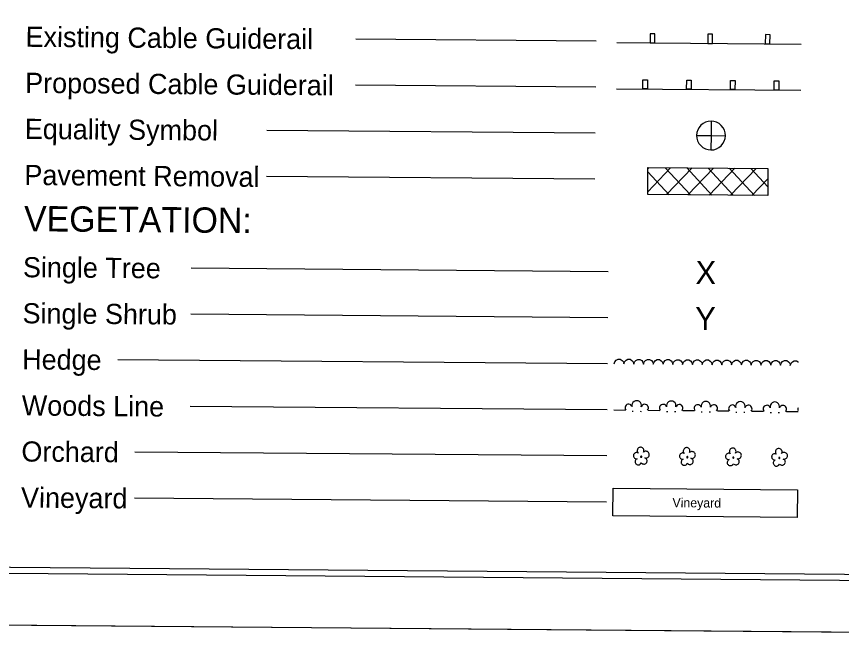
# Model space of a CAD drawing. Extents: x 1379453 to 1387082, y 594364 to 596664.
# Drawn here: x 1384828 to 1385545, y 594436 to 594983 of the extents above; entities that cross this region are included whole.
import ezdxf

# ---------------------------------------------------------------- set-up
doc = ezdxf.new("R2010")
doc.units = 0
for name, color, linetype in [('Sheet Cutting Line CELL', 7, 'Continuous'), ('Sheet Plot Border Inside CELL', 7, 'Continuous'), ('Sheet Plot Border Outside CELL', 7, 'Continuous'), ('Sheet Symbology CELL', 7, 'Continuous')]:
    doc.layers.add(name, color=color, linetype=linetype)

msp = doc.modelspace()

# ---------------------------------------------------------------- linework, layer by layer
at = {"layer": 'Sheet Cutting Line CELL'}
msp.add_line((1383695.45, 594463.89), (1387063.33, 594435.67), dxfattribs=at)
at = {"layer": 'Sheet Plot Border Inside CELL'}
msp.add_lwpolyline([(1383721.82, 594508.57), (1387054.71, 594480.65), (1387072.39, 596590.77), (1383739.5, 596618.7)], close=True, dxfattribs=at)
at = {"layer": 'Sheet Plot Border Outside CELL'}
msp.add_lwpolyline([(1383695.45, 594463.89), (1387063.33, 594435.67), (1387081.76, 596635.6), (1383713.88, 596663.81)], close=True, dxfattribs=at)
at = {"layer": 'Sheet Symbology CELL'}
for p, q in [((1385331.7, 594961.34), (1385123.11, 594963.08)), ((1385349.71, 594960.04), (1385509.71, 594958.7)), ((1385331.36, 594921.34), (1385122.77, 594923.09)), ((1385349.38, 594920.04), (1385509.37, 594918.7)), ((1385431.6, 594891.82), (1385431.49, 594879.32)), ((1385331.03, 594881.34), (1385045.79, 594883.73)), ((1385418.99, 594879.43), (1385431.49, 594879.32)), ((1385431.49, 594879.32), (1385431.39, 594866.82)), ((1385431.49, 594879.32), (1385443.99, 594879.22)), ((1385376.51, 594828.13), (1385376.71, 594851.53)), ((1385376.53, 594830.43), (1385396.41, 594851.37)), ((1385376.7, 594850.33), (1385377.81, 594851.52)), ((1385376.71, 594851.53), (1385480.9, 594850.66)), ((1385413.61, 594827.82), (1385391.81, 594851.41)), ((1385392.81, 594828), (1385415, 594851.21)), ((1385432.11, 594827.67), (1385410.4, 594851.25)), ((1385411.31, 594827.84), (1385433.6, 594851.05)), ((1385450.71, 594827.51), (1385428.9, 594851.09)), ((1385429.91, 594827.69), (1385452.1, 594850.9)), ((1385469.31, 594827.35), (1385447.4, 594850.94)), ((1385448.51, 594827.53), (1385470.6, 594850.74)), ((1385480.77, 594834.76), (1385466, 594850.78)), ((1385480.9, 594850.66), (1385480.71, 594827.26)), ((1385330.69, 594841.34), (1385045.45, 594843.73)), ((1385395.01, 594827.98), (1385376.68, 594847.93)), ((1385467.01, 594827.37), (1385480.83, 594841.86)), ((1385480.71, 594827.26), (1385376.51, 594828.13)), ((1385342.3, 594761.1), (1384980.06, 594764.14)), ((1385341.96, 594721.1), (1384979.72, 594724.14)), ((1385341.63, 594681.11), (1384916.27, 594684.67)), ((1385349.2, 594684.24), (1385350.81, 594685.13)), ((1385350.81, 594685.13), (1385352.71, 594685.11)), ((1385352.71, 594685.11), (1385354.3, 594684.1)), ((1385357.7, 594684.17), (1385359.31, 594685.06)), ((1385359.31, 594685.06), (1385361.21, 594685.04)), ((1385361.21, 594685.04), (1385362.8, 594684.03)), ((1385366.2, 594684.1), (1385367.81, 594684.99)), ((1385367.81, 594684.99), (1385369.71, 594684.97)), ((1385369.71, 594684.97), (1385371.3, 594683.96)), ((1385374.7, 594684.03), (1385376.31, 594684.92)), ((1385376.31, 594684.92), (1385378.21, 594684.9)), ((1385378.21, 594684.9), (1385379.8, 594683.89)), ((1385383.2, 594683.96), (1385384.81, 594684.84)), ((1385384.81, 594684.84), (1385386.71, 594684.83)), ((1385386.71, 594684.83), (1385388.3, 594683.81)), ((1385391.7, 594683.89), (1385393.31, 594684.77)), ((1385393.31, 594684.77), (1385395.21, 594684.76)), ((1385395.21, 594684.76), (1385396.8, 594683.74)), ((1385400.2, 594683.82), (1385401.81, 594684.7)), ((1385401.81, 594684.7), (1385403.71, 594684.69)), ((1385403.71, 594684.69), (1385405.3, 594683.67)), ((1385408.7, 594683.74), (1385410.31, 594684.63)), ((1385410.31, 594684.63), (1385412.21, 594684.61)), ((1385412.21, 594684.61), (1385413.8, 594683.6)), ((1385347.38, 594681.06), (1385347.99, 594682.95)), ((1385347.99, 594682.95), (1385349.2, 594684.24)), ((1385354.3, 594684.1), (1385355.39, 594682.79)), ((1385355.39, 594682.79), (1385355.78, 594681.09)), ((1385355.88, 594680.99), (1385356.49, 594682.88)), ((1385356.49, 594682.88), (1385357.7, 594684.17)), ((1385362.8, 594684.03), (1385363.89, 594682.72)), ((1385363.89, 594682.72), (1385364.28, 594681.02)), ((1385364.38, 594680.92), (1385364.99, 594682.81)), ((1385364.99, 594682.81), (1385366.2, 594684.1)), ((1385371.3, 594683.96), (1385372.39, 594682.65)), ((1385372.39, 594682.65), (1385372.78, 594680.94)), ((1385372.88, 594680.84), (1385373.49, 594682.74)), ((1385373.49, 594682.74), (1385374.7, 594684.03)), ((1385379.8, 594683.89), (1385380.89, 594682.58)), ((1385380.89, 594682.58), (1385381.28, 594680.87)), ((1385381.38, 594680.77), (1385381.99, 594682.67)), ((1385381.99, 594682.67), (1385383.2, 594683.96)), ((1385388.3, 594683.81), (1385389.39, 594682.51)), ((1385389.39, 594682.51), (1385389.78, 594680.8)), ((1385389.88, 594680.7), (1385390.49, 594682.6)), ((1385390.49, 594682.6), (1385391.7, 594683.89)), ((1385396.8, 594683.74), (1385397.89, 594682.43)), ((1385397.89, 594682.43), (1385398.28, 594680.73)), ((1385398.37, 594680.63), (1385398.99, 594682.53)), ((1385398.99, 594682.53), (1385400.2, 594683.82)), ((1385405.3, 594683.67), (1385406.39, 594682.36)), ((1385406.39, 594682.36), (1385406.78, 594680.66)), ((1385406.87, 594680.56), (1385407.49, 594682.45)), ((1385407.49, 594682.45), (1385408.7, 594683.74)), ((1385413.8, 594683.6), (1385414.89, 594682.29)), ((1385414.89, 594682.29), (1385415.28, 594680.59)), ((1385415.37, 594680.49), (1385415.99, 594682.38)), ((1385415.99, 594682.38), (1385417.2, 594683.67)), ((1385417.2, 594683.67), (1385418.81, 594684.56)), ((1385418.81, 594684.56), (1385420.71, 594684.54)), ((1385420.71, 594684.54), (1385422.3, 594683.53)), ((1385422.3, 594683.53), (1385423.39, 594682.22)), ((1385423.39, 594682.22), (1385423.77, 594680.52)), ((1385423.87, 594680.42), (1385424.49, 594682.31)), ((1385424.49, 594682.31), (1385425.7, 594683.6)), ((1385425.7, 594683.6), (1385427.31, 594684.49)), ((1385427.31, 594684.49), (1385429.21, 594684.47)), ((1385429.21, 594684.47), (1385430.8, 594683.46)), ((1385430.8, 594683.46), (1385431.89, 594682.15)), ((1385431.89, 594682.15), (1385432.27, 594680.45)), ((1385432.37, 594680.35), (1385432.99, 594682.24)), ((1385432.99, 594682.24), (1385434.2, 594683.53)), ((1385434.2, 594683.53), (1385435.81, 594684.42)), ((1385435.81, 594684.42), (1385437.71, 594684.4)), ((1385437.71, 594684.4), (1385439.3, 594683.39)), ((1385439.3, 594683.39), (1385440.39, 594682.08)), ((1385440.39, 594682.08), (1385440.77, 594680.38)), ((1385440.87, 594680.27), (1385441.49, 594682.17)), ((1385441.49, 594682.17), (1385442.7, 594683.46)), ((1385442.7, 594683.46), (1385444.31, 594684.35)), ((1385444.31, 594684.35), (1385446.21, 594684.33)), ((1385446.21, 594684.33), (1385447.8, 594683.32)), ((1385447.8, 594683.32), (1385448.89, 594682.01)), ((1385448.89, 594682.01), (1385449.27, 594680.3)), ((1385449.37, 594680.2), (1385449.99, 594682.1)), ((1385449.99, 594682.1), (1385451.2, 594683.39)), ((1385451.2, 594683.39), (1385452.81, 594684.27)), ((1385452.81, 594684.27), (1385454.71, 594684.26)), ((1385454.71, 594684.26), (1385456.3, 594683.25)), ((1385456.3, 594683.25), (1385457.39, 594681.94)), ((1385457.39, 594681.94), (1385457.77, 594680.23)), ((1385457.87, 594680.13), (1385458.49, 594682.03)), ((1385458.49, 594682.03), (1385459.7, 594683.32)), ((1385459.7, 594683.32), (1385461.31, 594684.2)), ((1385461.31, 594684.2), (1385463.21, 594684.19)), ((1385463.21, 594684.19), (1385464.8, 594683.17)), ((1385464.8, 594683.17), (1385465.89, 594681.86)), ((1385465.89, 594681.86), (1385466.27, 594680.16)), ((1385466.37, 594680.06), (1385466.99, 594681.96)), ((1385466.99, 594681.96), (1385468.2, 594683.25)), ((1385468.2, 594683.25), (1385469.81, 594684.13)), ((1385469.81, 594684.13), (1385471.71, 594684.12)), ((1385471.71, 594684.12), (1385473.3, 594683.1)), ((1385473.3, 594683.1), (1385474.39, 594681.79)), ((1385474.39, 594681.79), (1385474.77, 594680.09)), ((1385474.87, 594679.99), (1385475.49, 594681.88)), ((1385475.49, 594681.88), (1385476.7, 594683.17)), ((1385476.7, 594683.17), (1385478.31, 594684.06)), ((1385478.31, 594684.06), (1385480.21, 594684.05)), ((1385480.21, 594684.05), (1385481.8, 594683.03)), ((1385481.8, 594683.03), (1385482.89, 594681.72)), ((1385482.89, 594681.72), (1385483.27, 594680.02)), ((1385483.37, 594679.92), (1385483.99, 594681.81)), ((1385483.99, 594681.81), (1385485.2, 594683.1)), ((1385485.2, 594683.1), (1385486.81, 594683.99)), ((1385486.81, 594683.99), (1385488.71, 594683.97)), ((1385488.71, 594683.97), (1385490.3, 594682.96)), ((1385490.3, 594682.96), (1385491.39, 594681.65)), ((1385491.39, 594681.65), (1385491.77, 594679.95)), ((1385491.87, 594679.85), (1385492.49, 594681.74)), ((1385492.49, 594681.74), (1385493.7, 594683.03)), ((1385493.7, 594683.03), (1385495.31, 594683.92)), ((1385495.31, 594683.92), (1385497.21, 594683.9)), ((1385497.21, 594683.9), (1385498.8, 594682.89)), ((1385498.8, 594682.89), (1385499.89, 594681.58)), ((1385499.89, 594681.58), (1385500.27, 594679.88)), ((1385500.37, 594679.78), (1385500.99, 594681.67)), ((1385500.99, 594681.67), (1385502.2, 594682.96)), ((1385502.2, 594682.96), (1385503.81, 594683.85)), ((1385503.81, 594683.85), (1385505.71, 594683.83)), ((1385505.71, 594683.83), (1385507.3, 594682.82)), ((1385507.3, 594682.82), (1385507.4, 594682.72)), ((1385341.29, 594641.11), (1384979.05, 594644.14)), ((1385347.04, 594641.06), (1385357.04, 594640.98)), ((1385362.93, 594639.93), (1385363.93, 594639.92)), ((1385369.93, 594639.87), (1385370.93, 594639.86)), ((1385377.04, 594640.81), (1385387.04, 594640.72)), ((1385392.93, 594639.67), (1385393.93, 594639.67)), ((1385399.93, 594639.62), (1385400.93, 594639.61)), ((1385407.04, 594640.56), (1385417.04, 594640.47)), ((1385422.93, 594639.42), (1385423.93, 594639.41)), ((1385429.93, 594639.36), (1385430.93, 594639.36)), ((1385437.04, 594640.31), (1385447.04, 594640.22)), ((1385452.93, 594639.17), (1385453.93, 594639.16)), ((1385459.93, 594639.11), (1385460.93, 594639.1)), ((1385467.04, 594640.05), (1385477.04, 594639.97)), ((1385482.93, 594638.92), (1385483.93, 594638.91)), ((1385489.93, 594638.86), (1385490.93, 594638.85)), ((1385497.04, 594639.8), (1385507.04, 594639.72)), ((1385340.96, 594601.11), (1384931.1, 594604.54)), ((1385340.62, 594561.11), (1384930.76, 594564.54))]:
    msp.add_line(p, q, dxfattribs=at)
for points in [[(1387047.34, 596585.88), (1384047.45, 596611.02), (1384029.86, 594511.09), (1387029.75, 594485.96)], [(1385378.66, 594959.79), (1385382.66, 594959.76), (1385382.73, 594967.76), (1385378.73, 594967.79)], [(1385428.66, 594959.38), (1385432.66, 594959.34), (1385432.73, 594967.34), (1385428.73, 594967.37)], [(1385478.66, 594958.96), (1385482.66, 594958.92), (1385482.73, 594966.92), (1385478.73, 594966.96)], [(1385372.37, 594927.85), (1385376.37, 594927.81), (1385376.3, 594919.81), (1385372.3, 594919.85)], [(1385410.37, 594927.53), (1385414.37, 594927.49), (1385414.3, 594919.49), (1385410.3, 594919.53)], [(1385448.37, 594927.21), (1385452.37, 594927.18), (1385452.3, 594919.18), (1385448.3, 594919.21)], [(1385486.37, 594926.89), (1385490.37, 594926.86), (1385490.3, 594918.86), (1385486.3, 594918.89)]]:
    msp.add_lwpolyline(points, close=True, dxfattribs=at)
for points in [[(1385372.83, 594604.34), (1385373.14, 594604.94), (1385373.24, 594605.54), (1385373.15, 594606.14), (1385373.05, 594606.74), (1385372.76, 594607.24), (1385372.46, 594607.74), (1385371.97, 594608.15), (1385371.47, 594608.45), (1385370.77, 594608.66), (1385370.27, 594608.66), (1385369.67, 594608.57), (1385369.07, 594608.37), (1385368.57, 594608.08), (1385368.06, 594607.68), (1385367.76, 594607.08), (1385367.55, 594606.59), (1385367.45, 594605.99), (1385367.44, 594605.39), (1385367.54, 594604.79), (1385367.83, 594604.28), (1385368.23, 594603.68), (1385367.73, 594603.98), (1385367.13, 594604.09), (1385366.53, 594604.09), (1385366.03, 594603.9), (1385365.53, 594603.7), (1385365.03, 594603.31), (1385364.62, 594602.91), (1385364.32, 594602.41), (1385364.21, 594601.91), (1385364.11, 594601.21), (1385364.2, 594600.71), (1385364.4, 594600.21), (1385364.8, 594599.71), (1385365.09, 594599.31), (1385365.59, 594599), (1385366.19, 594598.7), (1385366.69, 594598.59), (1385367.29, 594598.59), (1385366.78, 594598.39), (1385366.28, 594598), (1385365.98, 594597.6), (1385365.77, 594597), (1385365.57, 594596.4), (1385365.56, 594595.9), (1385365.66, 594595.3), (1385365.95, 594594.8), (1385366.25, 594594.3), (1385366.65, 594593.89), (1385367.14, 594593.59), (1385367.64, 594593.38), (1385368.24, 594593.38), (1385368.84, 594593.37), (1385369.34, 594593.47), (1385369.85, 594593.87), (1385370.35, 594594.16), (1385370.86, 594595.06)], [(1385412.83, 594604.01), (1385413.14, 594604.6), (1385413.24, 594605.2), (1385413.15, 594605.8), (1385413.05, 594606.4), (1385412.76, 594606.91), (1385412.46, 594607.41), (1385411.97, 594607.81), (1385411.47, 594608.12), (1385410.77, 594608.32), (1385410.27, 594608.33), (1385409.67, 594608.23), (1385409.07, 594608.04), (1385408.56, 594607.74), (1385408.06, 594607.35), (1385407.76, 594606.75), (1385407.55, 594606.25), (1385407.45, 594605.65), (1385407.44, 594605.05), (1385407.54, 594604.45), (1385407.83, 594603.95), (1385408.23, 594603.35), (1385407.73, 594603.65), (1385407.13, 594603.75), (1385406.53, 594603.76), (1385406.03, 594603.56), (1385405.53, 594603.37), (1385405.02, 594602.97), (1385404.62, 594602.58), (1385404.32, 594602.08), (1385404.21, 594601.58), (1385404.11, 594600.88), (1385404.2, 594600.38), (1385404.4, 594599.88), (1385404.79, 594599.37), (1385405.09, 594598.97), (1385405.59, 594598.67), (1385406.19, 594598.36), (1385406.69, 594598.26), (1385407.29, 594598.25), (1385406.78, 594598.06), (1385406.28, 594597.66), (1385405.98, 594597.26), (1385405.77, 594596.67), (1385405.57, 594596.07), (1385405.56, 594595.57), (1385405.66, 594594.97), (1385405.95, 594594.46), (1385406.25, 594593.96), (1385406.65, 594593.56), (1385407.14, 594593.25), (1385407.64, 594593.05), (1385408.24, 594593.04), (1385408.84, 594593.04), (1385409.34, 594593.14), (1385409.85, 594593.53), (1385410.35, 594593.83), (1385410.86, 594594.72)], [(1385452.83, 594603.67), (1385453.14, 594604.27), (1385453.24, 594604.87), (1385453.15, 594605.47), (1385453.05, 594606.07), (1385452.76, 594606.57), (1385452.46, 594607.07), (1385451.96, 594607.48), (1385451.47, 594607.78), (1385450.77, 594607.99), (1385450.27, 594607.99), (1385449.67, 594607.9), (1385449.07, 594607.7), (1385448.56, 594607.41), (1385448.06, 594607.01), (1385447.75, 594606.41), (1385447.55, 594605.92), (1385447.45, 594605.32), (1385447.44, 594604.72), (1385447.54, 594604.12), (1385447.83, 594603.61), (1385448.23, 594603.01), (1385447.73, 594603.31), (1385447.13, 594603.42), (1385446.53, 594603.42), (1385446.03, 594603.23), (1385445.53, 594603.03), (1385445.02, 594602.64), (1385444.62, 594602.24), (1385444.32, 594601.74), (1385444.21, 594601.24), (1385444.11, 594600.54), (1385444.2, 594600.04), (1385444.4, 594599.54), (1385444.79, 594599.04), (1385445.09, 594598.64), (1385445.59, 594598.33), (1385446.18, 594598.03), (1385446.68, 594597.92), (1385447.28, 594597.92), (1385446.78, 594597.72), (1385446.28, 594597.33), (1385445.98, 594596.93), (1385445.77, 594596.33), (1385445.57, 594595.73), (1385445.56, 594595.23), (1385445.66, 594594.63), (1385445.95, 594594.13), (1385446.25, 594593.63), (1385446.64, 594593.22), (1385447.14, 594592.92), (1385447.64, 594592.71), (1385448.24, 594592.71), (1385448.84, 594592.7), (1385449.34, 594592.8), (1385449.84, 594593.2), (1385450.35, 594593.49), (1385450.85, 594594.39)], [(1385492.83, 594603.34), (1385493.14, 594603.93), (1385493.24, 594604.53), (1385493.15, 594605.13), (1385493.05, 594605.73), (1385492.75, 594606.24), (1385492.46, 594606.74), (1385491.96, 594607.14), (1385491.47, 594607.45), (1385490.77, 594607.65), (1385490.27, 594607.66), (1385489.67, 594607.56), (1385489.06, 594607.37), (1385488.56, 594607.07), (1385488.06, 594606.68), (1385487.75, 594606.08), (1385487.55, 594605.58), (1385487.44, 594604.98), (1385487.44, 594604.38), (1385487.53, 594603.78), (1385487.83, 594603.28), (1385488.22, 594602.67), (1385487.73, 594602.98), (1385487.13, 594603.08), (1385486.53, 594603.09), (1385486.03, 594602.89), (1385485.53, 594602.7), (1385485.02, 594602.3), (1385484.62, 594601.91), (1385484.31, 594601.41), (1385484.21, 594600.91), (1385484.1, 594600.21), (1385484.2, 594599.71), (1385484.4, 594599.21), (1385484.79, 594598.7), (1385485.09, 594598.3), (1385485.59, 594598), (1385486.18, 594597.69), (1385486.68, 594597.59), (1385487.28, 594597.58), (1385486.78, 594597.39), (1385486.28, 594596.99), (1385485.97, 594596.59), (1385485.77, 594596), (1385485.56, 594595.4), (1385485.56, 594594.9), (1385485.65, 594594.3), (1385485.95, 594593.79), (1385486.25, 594593.29), (1385486.64, 594592.89), (1385487.14, 594592.58), (1385487.64, 594592.38), (1385488.24, 594592.37), (1385488.84, 594592.37), (1385489.34, 594592.47), (1385489.84, 594592.86), (1385490.35, 594593.16), (1385490.85, 594594.05)], [(1385371.11, 594600.86), (1385370.81, 594600.86), (1385370.6, 594600.76), (1385370.4, 594600.66), (1385370.4, 594600.36), (1385370.4, 594600.16), (1385370.6, 594599.96), (1385370.9, 594599.96), (1385371.1, 594599.96), (1385371.3, 594600.15), (1385371.4, 594600.45), (1385371.3, 594600.65), (1385371.11, 594600.86)], [(1385370.86, 594595.06), (1385372.05, 594594.35), (1385372.65, 594594.14), (1385373.25, 594594.04), (1385373.85, 594594.13), (1385374.35, 594594.33), (1385374.85, 594594.62), (1385375.36, 594595.02), (1385375.66, 594595.52), (1385375.87, 594596.02), (1385376.07, 594596.61), (1385375.98, 594597.22), (1385375.88, 594597.82), (1385375.49, 594598.42), (1385375.19, 594598.82), (1385374.69, 594599.13), (1385374.09, 594599.43), (1385374.69, 594599.33), (1385375.39, 594599.32), (1385375.89, 594599.52), (1385376.5, 594599.81), (1385377, 594600.11), (1385377.4, 594600.6), (1385377.71, 594601.2), (1385377.81, 594601.8), (1385377.92, 594602.4), (1385377.82, 594603), (1385377.63, 594603.6), (1385377.23, 594604.1), (1385376.74, 594604.61), (1385376.24, 594604.91), (1385375.64, 594605.12), (1385375.04, 594605.22), (1385374.44, 594605.23), (1385373.84, 594605.03), (1385373.34, 594604.74), (1385372.83, 594604.34)], [(1385411.1, 594600.52), (1385410.8, 594600.52), (1385410.6, 594600.43), (1385410.4, 594600.33), (1385410.4, 594600.03), (1385410.4, 594599.83), (1385410.6, 594599.63), (1385410.9, 594599.62), (1385411.1, 594599.62), (1385411.3, 594599.82), (1385411.4, 594600.12), (1385411.3, 594600.32), (1385411.1, 594600.52)], [(1385410.86, 594594.72), (1385412.05, 594594.01), (1385412.65, 594593.81), (1385413.25, 594593.7), (1385413.85, 594593.8), (1385414.35, 594593.99), (1385414.85, 594594.29), (1385415.36, 594594.69), (1385415.66, 594595.18), (1385415.86, 594595.68), (1385416.07, 594596.28), (1385415.97, 594596.88), (1385415.88, 594597.48), (1385415.48, 594598.08), (1385415.19, 594598.49), (1385414.69, 594598.79), (1385414.09, 594599.1), (1385414.69, 594598.99), (1385415.39, 594598.98), (1385415.89, 594599.18), (1385416.5, 594599.48), (1385417, 594599.77), (1385417.4, 594600.27), (1385417.71, 594600.87), (1385417.81, 594601.46), (1385417.92, 594602.06), (1385417.82, 594602.66), (1385417.63, 594603.27), (1385417.23, 594603.77), (1385416.74, 594604.27), (1385416.24, 594604.58), (1385415.64, 594604.78), (1385415.04, 594604.89), (1385414.44, 594604.89), (1385413.84, 594604.7), (1385413.34, 594604.4), (1385412.83, 594604.01)], [(1385451.1, 594600.19), (1385450.8, 594600.19), (1385450.6, 594600.09), (1385450.4, 594599.99), (1385450.4, 594599.69), (1385450.4, 594599.49), (1385450.6, 594599.29), (1385450.9, 594599.29), (1385451.1, 594599.29), (1385451.3, 594599.48), (1385451.4, 594599.78), (1385451.3, 594599.98), (1385451.1, 594600.19)], [(1385450.85, 594594.39), (1385452.05, 594593.68), (1385452.65, 594593.47), (1385453.25, 594593.37), (1385453.85, 594593.46), (1385454.35, 594593.66), (1385454.85, 594593.95), (1385455.35, 594594.35), (1385455.66, 594594.85), (1385455.86, 594595.35), (1385456.07, 594595.94), (1385455.97, 594596.54), (1385455.88, 594597.15), (1385455.48, 594597.75), (1385455.19, 594598.15), (1385454.69, 594598.46), (1385454.09, 594598.76), (1385454.69, 594598.66), (1385455.39, 594598.65), (1385455.89, 594598.85), (1385456.49, 594599.14), (1385457, 594599.44), (1385457.4, 594599.93), (1385457.71, 594600.53), (1385457.81, 594601.13), (1385457.92, 594601.73), (1385457.82, 594602.33), (1385457.63, 594602.93), (1385457.23, 594603.43), (1385456.73, 594603.94), (1385456.24, 594604.24), (1385455.64, 594604.45), (1385455.04, 594604.55), (1385454.44, 594604.56), (1385453.84, 594604.36), (1385453.34, 594604.07), (1385452.83, 594603.67)], [(1385491.1, 594599.85), (1385490.8, 594599.85), (1385490.6, 594599.75), (1385490.4, 594599.66), (1385490.4, 594599.36), (1385490.4, 594599.16), (1385490.59, 594598.95), (1385490.89, 594598.95), (1385491.09, 594598.95), (1385491.3, 594599.15), (1385491.4, 594599.45), (1385491.3, 594599.65), (1385491.1, 594599.85)], [(1385490.85, 594594.05), (1385492.05, 594593.34), (1385492.65, 594593.14), (1385493.24, 594593.03), (1385493.85, 594593.13), (1385494.35, 594593.32), (1385494.85, 594593.62), (1385495.35, 594594.01), (1385495.66, 594594.51), (1385495.86, 594595.01), (1385496.07, 594595.61), (1385495.97, 594596.21), (1385495.88, 594596.81), (1385495.48, 594597.41), (1385495.18, 594597.82), (1385494.69, 594598.12), (1385494.09, 594598.43), (1385494.69, 594598.32), (1385495.39, 594598.31), (1385495.89, 594598.51), (1385496.49, 594598.81), (1385497, 594599.1), (1385497.4, 594599.6), (1385497.7, 594600.2), (1385497.81, 594600.79), (1385497.91, 594601.39), (1385497.82, 594601.99), (1385497.62, 594602.6), (1385497.23, 594603.1), (1385496.73, 594603.6), (1385496.24, 594603.91), (1385495.64, 594604.11), (1385495.04, 594604.22), (1385494.44, 594604.22), (1385493.84, 594604.03), (1385493.33, 594603.73), (1385492.83, 594603.34)], [(1385346.47, 594573.06), (1385506.47, 594571.72), (1385506.27, 594547.72), (1385346.27, 594549.06), (1385346.47, 594573.06)]]:
    msp.add_lwpolyline(points, dxfattribs=at)
for centre, radius, start, end in [((1385431.49, 594879.32), 12.5, 89.5144, 179.51894), ((1385431.49, 594879.32), 12.5, 359.5144, 89.51894), ((1385431.49, 594879.32), 12.5, 179.5144, 269.51894), ((1385431.49, 594879.32), 12.5, 269.5144, 359.51894), ((1385366.97, 594644.92), 4.12, 345.48377, 193.55626), ((1385396.97, 594644.67), 4.12, 345.48377, 193.55626), ((1385359.96, 594642.98), 3.16, 17.95497, 218.75153), ((1385373.96, 594642.86), 3.16, 320.2885, 161.08507), ((1385389.95, 594642.73), 3.16, 17.95497, 218.75153), ((1385403.95, 594642.61), 3.16, 320.2885, 161.08507), ((1385419.95, 594642.48), 3.16, 17.95497, 218.75153), ((1385426.97, 594644.42), 4.12, 345.48377, 193.55626), ((1385433.95, 594642.36), 3.16, 320.2885, 161.08507), ((1385449.95, 594642.23), 3.16, 17.95497, 218.75153), ((1385456.97, 594644.17), 4.12, 345.48377, 193.55626), ((1385463.95, 594642.11), 3.16, 320.2885, 161.08507), ((1385479.95, 594641.98), 3.16, 17.95497, 218.75153), ((1385486.96, 594643.92), 4.12, 345.48377, 193.55626), ((1385493.95, 594641.86), 3.16, 320.2885, 161.08507), ((1385509.95, 594641.72), 3.16, 155.77103, 203.269)]:
    msp.add_arc(centre, radius, start, end, dxfattribs=at)

# ---------------------------------------------------------------- texts
for s, height, rotation, p in [('Existing Cable Guiderail', 17.5, 359.52002, (1384836.17, 594956.41)), ('Proposed Cable Guiderail', 17.5, 359.52002, (1384835.83, 594916.41)), ('Equality Symbol', 17.5, 359.52002, (1384835.5, 594876.42)), ('Pavement Removal', 17.5, 359.52002, (1384835.16, 594836.42)), ('VEGETATION:', 22, 359.52002, (1384834.8, 594796.26)), ('Single Tree', 17.5, 359.52002, (1384833.91, 594756.31)), ('X', 20, 359.52002, (1385417.96, 594750.47)), ('Single Shrub', 17.5, 359.52002, (1384833.58, 594716.31)), ('Y', 20, 359.52002, (1385417.63, 594710.47)), ('Hedge', 17.5, 359.52002, (1384833.24, 594676.31)), ('Woods Line', 17.5, 359.52002, (1384832.91, 594636.32)), ('Orchard', 17.5, 359.52002, (1384832.57, 594596.32)), ('Vineyard', 17.5, 359.52002, (1384832.24, 594556.32)), ('Vineyard', 8, 359.52003, (1385397.99, 594556.63))]:
    msp.add_text(s, height=height, rotation=rotation, dxfattribs=at).set_placement(p)

doc.saveas('drawing.dxf')
